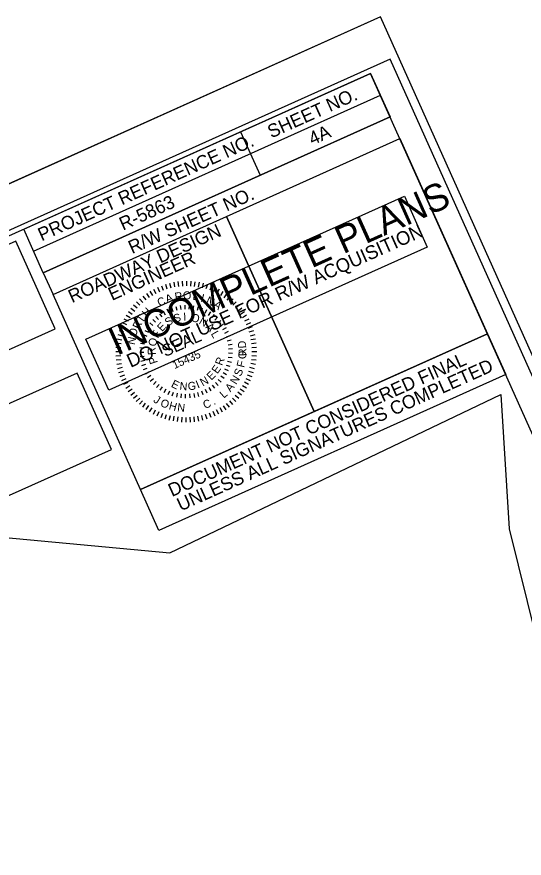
# Model space of a CAD drawing. Extents: x 553939 to 555925, y 502653 to 504347.
# Drawn here: x 555283.4 to 555550.4, y 503904.2 to 504346.6 of the extents above; entities that cross this region are included whole.
import ezdxf

# ---------------------------------------------------------------- set-up
doc = ezdxf.new("R2010")
doc.units = 0
for name, color, linetype in [('Prop Horizontal Alignment Curve and Spiral Data', 7, 'Continuous'), ('Prop Horizontal Alignment Direction Label', 7, 'Continuous'), ('Prop SS Cut Line', 7, 'Continuous'), ('Prop SS Fill Line', 7, 'Continuous'), ('Prop SS Transition Line', 7, 'Continuous'), ('Scratch_Level_3', 7, 'Continuous'), ('Scratch_Level_9', 7, 'Continuous'), ('Sheet Clip Boundary CELL', 7, 'Continuous'), ('Sheet Sticker Exception Certification CELL', 7, 'Continuous'), ('Sheet Sticker Incomplete CELL', 7, 'Continuous')]:
    doc.layers.add(name, color=color, linetype=linetype)

msp = doc.modelspace()

# ---------------------------------------------------------------- linework, layer by layer
at = {"layer": 'Prop Horizontal Alignment Curve and Spiral Data'}
msp.add_lwpolyline([(555041.64, 504036.97), (555059.67, 503996.82), (555333.29, 504119.14), (555315.26, 504159.3), (555041.64, 504036.97)], dxfattribs=at)
at = {"layer": 'Prop Horizontal Alignment Direction Label'}
msp.add_lwpolyline([(555474.87, 504346.62), (553938.64, 503656.8), (554389.23, 502653.32), (555925.47, 503343.14)], close=True, dxfattribs=at)
at = {"layer": 'Prop SS Cut Line'}
for p, q in [((555292.25, 504223.45), (555474.75, 504305.4)), ((555297.37, 504212.05), (555479.87, 504294)), ((555297.37, 504212.05), (555479.87, 504294)), ((555401.21, 504286.08), (555411.45, 504263.27)), ((555393.76, 504241.63), (555439.82, 504139.05)), ((555297.37, 504212.05), (555302.49, 504200.65))]:
    msp.add_line(p, q, dxfattribs=at)
for points in [[(555469.6, 504316.85), (554101.23, 503702.4), (554531.34, 502744.54), (555899.72, 503358.98)], [(555287.11, 504234.9), (555469.6, 504316.85), (555479.87, 504294), (555297.37, 504212.05)], [(555393.76, 504241.63), (555484.99, 504282.59), (555531.07, 504179.96), (555439.84, 504139)], [(555302.49, 504200.65), (555393.76, 504241.63), (555439.84, 504139), (555348.57, 504098.02)]]:
    msp.add_lwpolyline(points, close=True, dxfattribs=at)
at = {"layer": 'Prop SS Fill Line'}
msp.add_lwpolyline([(555479.96, 504324.29), (553959.7, 503641.65), (554391.9, 502679.13), (555912.16, 503361.78)], close=True, dxfattribs=at)
at = {"layer": 'Prop SS Transition Line'}
msp.add_lwpolyline([(555048.1, 504067.77), (555303.57, 504182.49), (555282.87, 504228.59), (555027.39, 504113.87)], close=True, dxfattribs=at)
at = {"layer": 'Scratch_Level_3'}
for p, q in [((555357.45, 504204.39), (555358.48, 504202.08)), ((555359.52, 504205.24), (555360.41, 504202.88)), ((555361.64, 504205.97), (555362.38, 504203.56)), ((555363.79, 504206.57), (555364.39, 504204.11)), ((555365.98, 504207.03), (555366.44, 504204.55)), ((555368.2, 504207.37), (555368.5, 504204.85)), ((555370.43, 504207.56), (555370.58, 504205.04)), ((555372.67, 504207.62), (555372.67, 504205.1)), ((555374.91, 504207.55), (555374.75, 504205.03)), ((555377.14, 504207.34), (555376.83, 504204.83)), ((555379.35, 504207), (555378.89, 504204.52)), ((555381.54, 504206.53), (555380.93, 504204.07)), ((555383.7, 504205.92), (555382.94, 504203.51)), ((555385.81, 504205.18), (555384.91, 504202.82)), ((555387.88, 504204.32), (555386.84, 504202.02)), ((555349.79, 504199.79), (555351.34, 504197.79)), ((555351.59, 504201.11), (555353.02, 504199.02)), ((555353.48, 504202.32), (555354.78, 504200.15)), ((555355.43, 504203.41), (555356.6, 504201.17)), ((555389.89, 504203.34), (555388.71, 504201.1)), ((555391.84, 504202.23), (555390.53, 504200.07)), ((555393.72, 504201.01), (555392.28, 504198.93)), ((555395.52, 504199.68), (555393.96, 504197.69)), ((555344.89, 504195.19), (555346.78, 504193.51)), ((555346.43, 504196.82), (555348.21, 504195.03)), ((555348.06, 504198.35), (555349.73, 504196.45)), ((555369.4, 504194.77), (555369.68, 504192.68)), ((555371.76, 504194.97), (555371.83, 504192.86)), ((555374.12, 504194.93), (555373.99, 504192.83)), ((555397.24, 504198.24), (555395.56, 504196.36)), ((555398.87, 504196.7), (555397.07, 504194.92)), ((555400.4, 504195.07), (555398.5, 504193.4)), ((555342.12, 504191.68), (555344.2, 504190.24)), ((555343.45, 504193.48), (555345.44, 504191.91)), ((555358.51, 504190.52), (555359.72, 504188.8)), ((555360.5, 504191.78), (555361.54, 504189.95)), ((555362.61, 504192.85), (555363.47, 504190.93)), ((555363.47, 504190.93), (555362.61, 504192.85)), ((555364.81, 504193.71), (555365.48, 504191.71)), ((555367.08, 504194.35), (555367.56, 504192.3)), ((555376.46, 504194.67), (555376.13, 504192.59)), ((555378.78, 504194.19), (555378.24, 504192.15)), ((555381.03, 504193.48), (555380.3, 504191.5)), ((555383.2, 504192.56), (555382.29, 504190.66)), ((555385.28, 504191.43), (555384.19, 504189.63)), ((555401.83, 504193.34), (555399.83, 504191.79)), ((555403.15, 504191.54), (555401.07, 504190.11)), ((555339.8, 504187.85), (555342.03, 504186.67)), ((555340.9, 504189.8), (555343.06, 504188.49)), ((555354.93, 504187.44), (555356.45, 504185.98)), ((555356.65, 504189.07), (555358.02, 504187.47)), ((555387.23, 504190.11), (555385.97, 504188.42)), ((555389.05, 504188.6), (555387.63, 504187.05)), ((555390.72, 504186.93), (555389.15, 504185.52)), ((555404.36, 504189.65), (555402.2, 504188.35)), ((555405.46, 504187.7), (555403.22, 504186.53)), ((555337.21, 504181.66), (555339.62, 504180.9)), ((555337.95, 504183.77), (555340.31, 504182.87)), ((555338.81, 504185.84), (555341.11, 504184.8)), ((555350.84, 504181.69), (555352.71, 504180.72)), ((555352.01, 504183.73), (555353.79, 504182.59)), ((555353.38, 504185.66), (555355.04, 504184.36)), ((555392.22, 504185.1), (555390.52, 504183.85)), ((555393.53, 504183.14), (555391.72, 504182.06)), ((555406.43, 504185.69), (555404.13, 504184.65)), ((555407.29, 504183.61), (555404.92, 504182.72)), ((555408.01, 504181.49), (555405.6, 504180.75)), ((555336.13, 504177.31), (555338.61, 504176.85)), ((555336.61, 504179.5), (555339.06, 504178.89)), ((555349.1, 504177.3), (555351.12, 504176.72)), ((555349.86, 504179.54), (555351.82, 504178.76)), ((555394.65, 504181.06), (555392.75, 504180.15)), ((555395.56, 504178.88), (555393.58, 504178.16)), ((555408.61, 504179.34), (555406.16, 504178.74)), ((555409.07, 504177.15), (555406.59, 504176.69)), ((555335.58, 504172.87), (555338.1, 504172.71)), ((555335.79, 504175.1), (555338.3, 504174.78)), ((555348.24, 504172.67), (555350.34, 504172.48)), ((555348.56, 504175), (555350.63, 504174.62)), ((555394.2, 504176.17), (555396.24, 504176.7)), ((555396.73, 504174.31), (555394.65, 504173.99)), ((555409.41, 504174.93), (555406.89, 504174.63)), ((555409.6, 504172.7), (555407.08, 504172.55)), ((555335.51, 504170.63), (555338.04, 504170.62)), ((555335.57, 504168.39), (555338.09, 504168.53)), ((555348.15, 504170.3), (555350.26, 504170.32)), ((555348.29, 504167.95), (555350.38, 504168.17)), ((555396.98, 504171.96), (555394.88, 504171.84)), ((555397, 504169.6), (555394.9, 504169.69)), ((555409.59, 504168.22), (555407.07, 504168.38)), ((555409.66, 504170.46), (555407.14, 504170.46)), ((555335.77, 504166.16), (555338.28, 504166.46)), ((555336.1, 504163.94), (555338.59, 504164.39)), ((555348.65, 504165.61), (555350.71, 504166.04)), ((555349.24, 504163.33), (555351.25, 504163.95)), ((555396.37, 504164.93), (555394.32, 504165.41)), ((555396.8, 504167.25), (555394.72, 504167.53)), ((555409.04, 504163.78), (555406.56, 504164.24)), ((555409.39, 504165.99), (555406.88, 504166.3)), ((555336.56, 504161.75), (555339.02, 504162.35)), ((555337.16, 504159.59), (555339.58, 504160.34)), ((555350.04, 504161.11), (555351.99, 504161.92)), ((555351.06, 504158.97), (555352.91, 504159.97)), ((555393.77, 504158.36), (555391.95, 504159.41)), ((555394.85, 504160.47), (555392.93, 504161.33)), ((555395.72, 504162.66), (555393.73, 504163.34)), ((555407.96, 504159.43), (555405.55, 504160.19)), ((555408.57, 504161.59), (555406.12, 504162.2)), ((555337.89, 504157.48), (555340.25, 504158.37)), ((555338.74, 504155.4), (555341.05, 504156.43)), ((555352.28, 504156.95), (555354.03, 504158.12)), ((555353.68, 504155.05), (555355.31, 504156.39)), ((555391.04, 504154.52), (555389.45, 504155.9)), ((555392.5, 504156.38), (555390.78, 504157.6)), ((555406.37, 504155.25), (555404.06, 504156.29)), ((555407.23, 504157.32), (555404.87, 504158.22)), ((555339.72, 504153.39), (555341.96, 504154.55)), ((555340.81, 504151.43), (555342.98, 504152.73)), ((555342.02, 504149.55), (555344.11, 504150.98)), ((555355.27, 504153.3), (555356.76, 504154.79)), ((555357.01, 504151.71), (555358.35, 504153.34)), ((555358.9, 504150.3), (555360.08, 504152.04)), ((555360.92, 504149.07), (555361.93, 504150.92)), ((555383.63, 504148.74), (555382.68, 504150.62)), ((555385.68, 504149.91), (555384.56, 504151.69)), ((555387.61, 504151.27), (555386.32, 504152.94)), ((555389.4, 504152.81), (555387.95, 504154.34)), ((555403.06, 504149.41), (555400.98, 504150.85)), ((555404.28, 504151.29), (555402.12, 504152.6)), ((555405.38, 504153.24), (555403.15, 504154.42)), ((555343.35, 504147.74), (555345.34, 504149.29)), ((555344.78, 504146.02), (555346.68, 504147.69)), ((555346.31, 504144.38), (555348.1, 504146.17)), ((555363.05, 504148.05), (555363.87, 504149.98)), ((555365.26, 504147.23), (555365.89, 504149.24)), ((555367.55, 504146.63), (555367.98, 504148.69)), ((555369.88, 504146.26), (555370.11, 504148.35)), ((555372.24, 504146.11), (555372.27, 504148.22)), ((555374.6, 504146.19), (555374.43, 504148.29)), ((555376.55, 504148.57), (555376.92, 504146.49)), ((555379.24, 504147.03), (555378.66, 504149.05)), ((555381.48, 504147.78), (555380.71, 504149.74)), ((555398.75, 504144.26), (555396.96, 504146.06)), ((555400.28, 504145.89), (555398.4, 504147.57)), ((555401.72, 504147.61), (555399.74, 504149.17)), ((555347.94, 504142.85), (555349.62, 504144.73)), ((555349.65, 504141.41), (555351.22, 504143.39)), ((555351.46, 504140.07), (555352.89, 504142.15)), ((555393.58, 504139.98), (555392.15, 504142.06)), ((555395.39, 504141.3), (555393.84, 504143.3)), ((555397.11, 504142.73), (555395.44, 504144.63)), ((555353.33, 504138.86), (555354.64, 504141.01)), ((555355.28, 504137.75), (555356.46, 504139.99)), ((555357.29, 504136.77), (555358.34, 504139.07)), ((555359.36, 504135.91), (555360.26, 504138.27)), ((555361.48, 504135.17), (555362.23, 504137.58)), ((555383.54, 504135.12), (555382.79, 504137.53)), ((555385.66, 504135.85), (555384.76, 504138.21)), ((555387.73, 504136.7), (555386.7, 504139)), ((555389.75, 504137.67), (555388.58, 504139.91)), ((555391.7, 504138.77), (555390.4, 504140.94)), ((555363.63, 504134.56), (555364.24, 504137.01)), ((555365.82, 504134.09), (555366.28, 504136.57)), ((555368.03, 504133.74), (555368.35, 504136.25)), ((555370.27, 504133.54), (555370.42, 504136.06)), ((555372.5, 504133.47), (555372.51, 504135.99)), ((555374.74, 504133.53), (555374.6, 504136.05)), ((555376.97, 504133.72), (555376.67, 504136.24)), ((555379.19, 504134.06), (555378.74, 504136.54)), ((555381.38, 504134.52), (555380.78, 504136.98))]:
    msp.add_line(p, q, dxfattribs=at)
at = {"layer": 'Scratch_Level_9'}
msp.add_line((555474.87, 504346.62), (553938.64, 503656.8), dxfattribs=at)
at = {"layer": 'Sheet Clip Boundary CELL'}
msp.add_lwpolyline([(554122.43, 503695.68), (555128.42, 504154.2), (555095.7, 504120), (555113.65, 504088.12), (555364.03, 504064.84), (555538.05, 504147.98), (555542.54, 504077.37), (555561.42, 504000.98), (555610.11, 503951.13), (555644.95, 503906.87), (555662.42, 503867.97), (555642.54, 503853.07), (555814.87, 503478.7), (555868.57, 503357.36), (555699.98, 503280.3), (555094.66, 503015.3), (554864.55, 502951)], dxfattribs=at)
msp.add_lwpolyline([(555608.35, 503927.62), (555814.87, 503478.7), (555868.57, 503357.36), (555699.98, 503280.3), (555094.66, 503015.3), (554759.27, 502917.8), (554683.01, 502878.56), (554582.25, 502838.31), (554549.81, 502954), (554532.1, 502969.19), (554525.96, 503000.02), (554442.4, 502999.26), (554417.71, 503015.86), (554346.87, 503170.59), (554325.2, 503273.41), (554285.23, 503305.85), (554122.43, 503695.68), (555128.42, 504154.2), (555095.7, 504120), (555113.65, 504088.12), (555364.03, 504064.84), (555538.05, 504147.98), (555542.54, 504077.37), (555561.42, 504000.98)], close=True, dxfattribs=at)
at = {"layer": 'Sheet Sticker Exception Certification CELL'}
for p, q in [((555348.57, 504098.02), (555531.06, 504179.96)), ((555531.06, 504179.95), (555540.69, 504158.51)), ((555540.68, 504158.52), (555358.2, 504076.58)), ((555358.2, 504076.58), (555348.57, 504098.02))]:
    msp.add_line(p, q, dxfattribs=at)
at = {"layer": 'Sheet Sticker Incomplete CELL'}
msp.add_lwpolyline([(555331.81, 504150.28), (555319.77, 504177.08), (555487.4, 504252.35), (555499.43, 504225.55)], close=True, dxfattribs=at)

# ---------------------------------------------------------------- texts
at = {"layer": 'Prop SS Cut Line'}
for s, p in [('SHEET NO.', (555417.33, 504282.63)), ('PROJECT REFERENCE NO.', (555296.5, 504228.49)), ('R/W SHEET NO.', (555344.05, 504221.83)), ('ROADWAY DESIGN', (555312.45, 504196.02)), ('ENGINEER', (555333.5, 504197.2))]:
    msp.add_text(s, height=7, rotation=24.1816, dxfattribs=at).set_placement(p)
at = {"layer": 'Prop SS Transition Line'}
for s, p in [('4A', (555438.95, 504278.97)), ('R-5863', (555339.27, 504234.15))]:
    msp.add_text(s, height=7, rotation=24.1816, dxfattribs=at).set_placement(p)
at = {"layer": 'Scratch_Level_3'}
for s, height, rotation, p in [('C', 4.21, 21.4587, (555358.31, 504194.21)), ('A', 4.21, 21.4587, (555362.55, 504196.01)), ('R', 4.21, 9.4494, (555366.87, 504197.26)), ('O', 4.21, 6.3926, (555371.09, 504197.82)), ('L', 4.21, 353.2563, (555375.76, 504197.86)), ('I', 4.21, 343.6808, (555379.86, 504197.01)), ('N', 4.21, 334.3864, (555382.59, 504196.06)), ('A', 4.21, 324.6188, (555386.4, 504194.36)), ('T', 4.21, 54.6013, (555349.43, 504185.26)), ('H', 4.21, 45.1694, (555351.77, 504188.32)), ('S', 4.21, 16.4536, (555366.58, 504185.77)), ('I', 4.21, 1.1574, (555371.03, 504186.77)), ('O', 4.21, 345.8611, (555374.8, 504186.66)), ('R', 4.21, 62.7623, (555347.8, 504181.95)), ('E', 4.21, 47.0461, (555359.86, 504180.8)), ('S', 4.21, 31.7499, (555362.88, 504183.73)), ('N', 4.21, 330.5649, (555378.91, 504185.41)), ('O', 4.21, 75.819, (555346.18, 504178.12)), ('F', 4.21, 62.3424, (555357.76, 504177.25)), ('A', 4.21, 315.2686, (555382.42, 504183.2)), ('L', 4.21, 299.9724, (555385.37, 504179.96)), ('N', 4.21, 77.7785, (555345.42, 504173.89)), ('O', 4.21, 77.6386, (555356.59, 504173.01)), ('SEAL', 6.318, 24.1017, (555361.48, 504167.65)), ('R', 4.21, 92.9348, (555356.62, 504168.88)), (' RD', 4.209, 93.7742, (555404.54, 504166.76)), ('15435', 4.209, 24.1017, (555366.37, 504161.36)), ('O ', 4.209, 85.1014, (555403.99, 504166.49)), ('P', 4.21, 108.2311, (555357.74, 504164.81)), ('E', 4.21, 54.8955, (555388.98, 504158.6)), ('R', 4.21, 68.6666, (555391.45, 504162.91)), ('F', 4.21, 76.3088, (555403.04, 504161.9)), ('E', 4.21, 44.9097, (555385.78, 504155.19)), ('S', 4.21, 67.4262, (555401.3, 504157.21)), ('E', 4.21, 334.1718, (555364.28, 504152.18)), ('I', 4.21, 21.8879, (555378.63, 504151.12)), ('N', 4.21, 29.5176, (555381.29, 504152.16)), ('N', 4.21, 58.5435, (555398.9, 504152.93)), ('N', 4.21, 355.0269, (555368.94, 504150.42)), ('G', 4.21, 3.7931, (555373.5, 504150.3)), ('A', 4.21, 49.7209, (555395.84, 504149.05)), ('J', 4.21, 328.0368, (555354.96, 504144.25)), ('L', 4.21, 40.7184, (555392.32, 504145.79)), ('O', 4.21, 336.1086, (555358.53, 504142.17)), ('H', 4.21, 344.7513, (555363.11, 504140.34)), ('N', 4.21, 353.4239, (555367.68, 504139.26)), ('C', 4.21, 20.1917, (555382.29, 504140.41)), ('.', 4.21, 27.934, (555387.11, 504142.44))]:
    msp.add_text(s, height=height, rotation=rotation, dxfattribs=at).set_placement(p)
at = {"layer": 'Sheet Sticker Exception Certification CELL'}
for s, p in [('DOCUMENT NOT CONSIDERED FINAL', (555365.03, 504094.07)), ('UNLESS ALL SIGNATURES COMPLETED', (555369.66, 504086.5))]:
    msp.add_text(s, height=7, rotation=24.1816, dxfattribs=at).set_placement(p)
at = {"layer": 'Sheet Sticker Incomplete CELL'}
for s, height, p in [('INCOMPLETE PLANS', 14.4, (555336.03, 504168.23)), ('DO NOT USE FOR R/W ACQUISITION', 7.2, (555343.29, 504161.97))]:
    msp.add_text(s, height=height, rotation=24.1816, dxfattribs=at).set_placement(p)

doc.saveas('drawing.dxf')
